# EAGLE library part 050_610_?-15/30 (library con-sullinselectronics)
.050 DIP EDGE CARD CONNECTOR .050 [1.27mm] CONTACT CENTERS .610" INSULATEOR HEIGHT Source: .050 DIP EDGE CARD.pdf
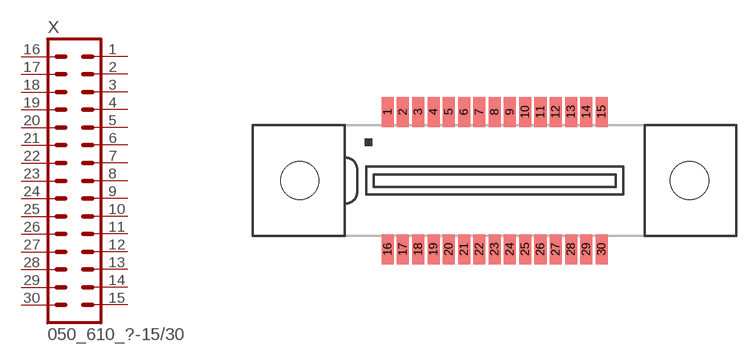
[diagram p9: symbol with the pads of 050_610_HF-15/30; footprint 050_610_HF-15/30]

Designator prefix X

## 050_610_HF-15/30 (OC_FARNELL: unknown; OC_NEWARK: unknown)  [050_610_HF-15/30]
1  1  pas
2  2  pas
3  3  pas
4  4  pas
5  5  pas
6  6  pas
7  7  pas
8  8  pas
9  9  pas
10  10  pas
11  11  pas
12  12  pas
13  13  pas
14  14  pas
15  15  pas
16  16  pas
17  17  pas
18  18  pas
19  19  pas
20  20  pas
21  21  pas
22  22  pas
23  23  pas
24  24  pas
25  25  pas
26  26  pas
27  27  pas
28  28  pas
29  29  pas
30  30  pas

## Footprint 050_610_HF-15/30 (pad centres in mm)
.050 DIP EDGE CARD CONNECTOR SURFACE MOUNT .050 [1.27mm] CONTACT CENTERS .610" INSULATEOR HEIGHT Source: .050 DIP EDGE CARD.pdf
smd 1 x 2.5: 1 -8.89,5.715; 2 -7.62,5.715; 3 -6.35,5.715; 4 -5.08,5.715; 5 -3.81,5.715; 6 -2.54,5.715; 7 -1.27,5.715; 8 0,5.715; 9 1.27,5.715; 10 2.54,5.715; 11 3.81,5.715; 12 5.08,5.715; 13 6.35,5.715; 14 7.62,5.715; 15 8.89,5.715; 16 -8.89,-5.715; 17 -7.62,-5.715; 18 -6.35,-5.715; 19 -5.08,-5.715; 20 -3.81,-5.715; 21 -2.54,-5.715; 22 -1.27,-5.715; 23 0,-5.715; 24 1.27,-5.715; 25 2.54,-5.715; 26 3.81,-5.715; 27 5.08,-5.715; 28 6.35,-5.715; 29 7.62,-5.715; 30 8.89,-5.715
hole 3.18 at -16.205,0
hole 3.18 at 16.205,0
